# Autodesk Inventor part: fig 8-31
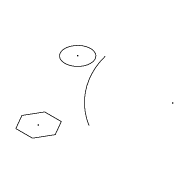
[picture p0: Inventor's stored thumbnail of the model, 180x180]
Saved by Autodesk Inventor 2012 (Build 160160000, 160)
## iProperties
Shininess: 77.0
Angle Display Precision: 2
Document Length Units: 11269
Document Angle Units: 11279
Document Time Units: 11290
Document Mass Units: 11283
Document Length Units Precision: 3
Document Angle Units Precision: 2
Created: 2001-12
Part Number: fig 8-31
Document SubType Name: Modeling
Designer: CADSoft
Density: 1 g/cm^3
Material: Default
Density: 0.0
Volumn: 0.0
Area: 0.0
PropertySet Name: Model Information
Control State: 0
Master: False
Checked Out: False
Author: CADSoft
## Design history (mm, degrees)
workplane "Work Plane3"
workplane "Work Plane4"
sketch "Sketch12"
  geometry: L1 (0, 10.598)-(9.178, -5.299); L2 (9.178, -5.299)-(-9.178, -5.299); L3 (-9.178, -5.299)-(0, 10.598); 1 further point
  constraints: 6 end point, 5 other
workplane "Work Plane5"
workplane "Work Plane6"
workplane "Work Plane7"
sketch "Sketch16"
  geometry: A1 r 72.799 centre (23.007, 110.594) between (0, 41.527) and (70, 54.995); 1 further point
  constraints: 2 point on circle, 1 centre point
body "Solid1"
sketch "Sketch1"
  geometry: L1 (19.387, 0)-(9.693, -16.79); L2 (9.693, -16.79)-(-9.693, -16.79); L3 (-9.693, -16.79)-(-19.387, 0); L4 (-19.387, 0)-(-9.693, 16.79); L5 (-9.693, 16.79)-(9.693, 16.79); L6 (9.693, 16.79)-(19.387, 0); 1 further point
  constraints: 12 end point, 11 other
sketch "Sketch2"
  geometry: C1 r 15 at (23.06, 22.535)
  constraints: 1 centre point
